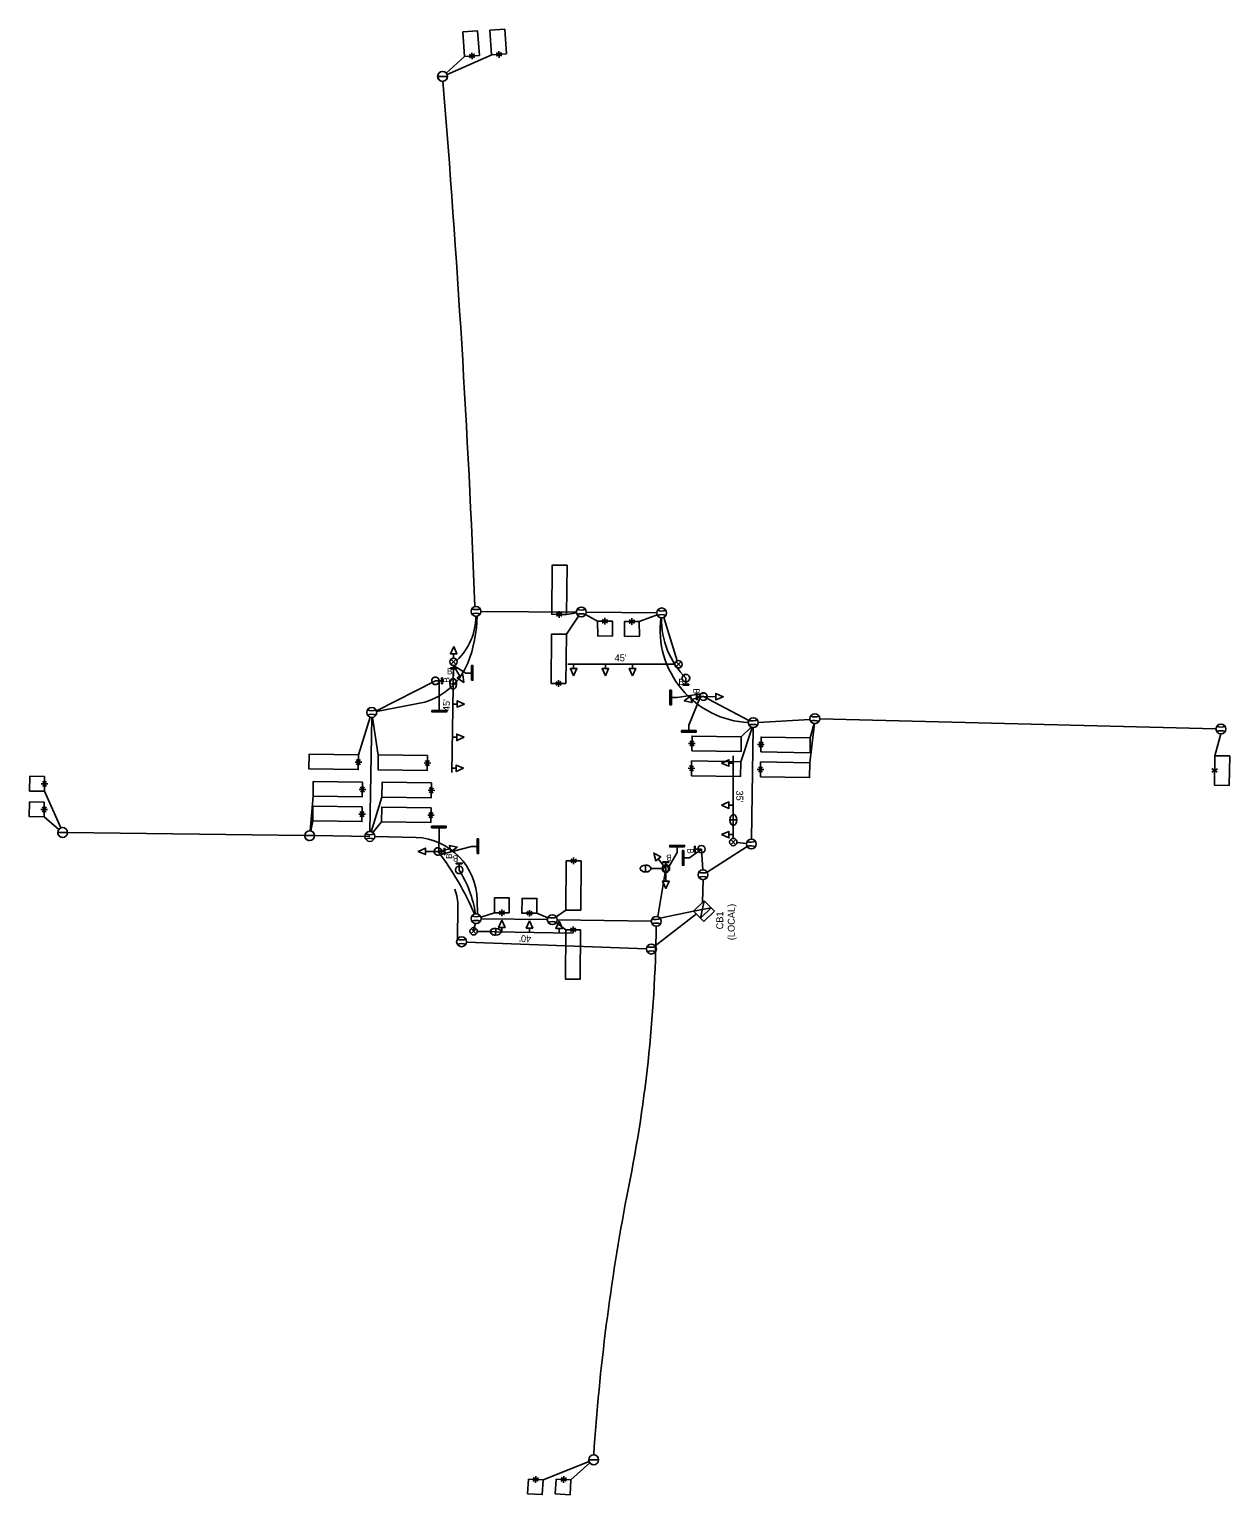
# Model space of a CAD drawing. Extents: x 596176 to 605330, y 332416 to 402398.
# Drawn here: x 604842 to 605330, y 332416 to 333011 of the extents above; entities that cross this region are included whole.
import ezdxf

# ---------------------------------------------------------------- set-up
doc = ezdxf.new("R2010")
doc.units = 0
for name, color, linetype in [('P_LTG', 7, 'Continuous'), ('P_SIG', 7, 'Continuous'), ('P_SIG_Bold', 7, 'Continuous'), ('P_SIG_Conduit', 7, 'Continuous'), ('P_SIG_IC', 7, 'Continuous'), ('P_SIG_Loops', 7, 'Continuous'), ('P_SIG_Text', 7, 'Continuous')]:
    doc.layers.add(name, color=color, linetype=linetype)

# ---------------------------------------------------------------- blocks, each defined once
blk = doc.blocks.new('CONTROL CABINET')
at = {"layer": 'P_SIG'}
for p, q in [((-0.229, 0.305), (0.229, 0.305)), ((-0.229, -0.152), (-0.229, 0.305)), ((-0.229, 0.152), (0.229, 0.152)), ((-0.229, -0.152), (0.229, 0.152)), ((0.229, -0.152), (-0.229, 0.152)), ((0.229, 0.305), (0.229, -0.152)), ((0.229, -0.152), (-0.229, -0.152))]:
    blk.add_line(p, q, dxfattribs=at)
blk = doc.blocks.new('BASE - PEDESTRIAN')
at = {"layer": 'P_SIG'}
blk.add_circle((0, 0.1), 4.57, dxfattribs=at)
blk = doc.blocks.new('_U332')
at = {"layer": 'P_SIG_Bold'}
for p, q in [((-3.429, 0), (-0.114, 0)), ((-0.081, 0.081), (0.081, -0.081)), ((0.081, 0.081), (-0.081, -0.081))]:
    blk.add_line(p, q, dxfattribs=at)
blk.add_circle((0, 0), 0.114, dxfattribs=at)
blk.add_text("45'", height=0.2134, dxfattribs=at).set_placement((-1.978, 0.092))
blk = doc.blocks.new('HEAD - TEMPORARY')
at = {"layer": 'P_SIG'}
blk.add_line((5.4, 0), (0, 0), dxfattribs=at)
blk.add_lwpolyline([(14.4, 0), (5.4, -4), (5.4, 4)], close=True, dxfattribs=at)
blk = doc.blocks.new('_U227')
at = {"layer": 'P_SIG'}
blk.add_circle((0, 0), 6.1, dxfattribs=at)
for centre, start, end in [((-15.5, 0.1), 336.6741, 22.5272), ((15.5, 0.1), 157.5751, 203.4282)]:
    blk.add_arc(centre, 13.3, start, end, dxfattribs=at)
blk = doc.blocks.new('_U226')
at = {"layer": 'P_SIG'}
blk.add_line((0, 6.1), (0, -6.1), dxfattribs=at)
blk.add_lwpolyline([(0, -6.1), (0, 6.1)], dxfattribs=at)
blk.add_circle((0, 0), 6.1, dxfattribs=at)
for start, end in [(89.7008, 180), (180, 269.7008)]:
    blk.add_arc((0, 0), 6.1, start, end, dxfattribs=at)
blk = doc.blocks.new('_U306')
at = {"layer": 'P_SIG_Loops'}
for p, q in [((-0.055, -0.084), (0.052, 0.081)), ((0.056, -0.083), (-0.053, 0.082)), ((0, 0), (0, -0.229)), ((-0.105, -0.001), (0.099, -0.001))]:
    blk.add_line(p, q, dxfattribs=at)
blk.add_lwpolyline([(0, -0.229), (1.524, -0.229), (1.524, 0.229), (0, 0.229)], close=True, dxfattribs=at)
blk = doc.blocks.new('_U325')
at = {"layer": 'P_SIG_Loops'}
for p, q in [((-0.055, -0.084), (0.052, 0.081)), ((0.056, -0.083), (-0.053, 0.082)), ((-0.105, -0.001), (0.099, -0.001))]:
    blk.add_line(p, q, dxfattribs=at)
blk.add_lwpolyline([(0, -0.229), (0.762, -0.229), (0.762, 0.229), (0, 0.229)], close=True, dxfattribs=at)
blk = doc.blocks.new('_U312')
at = {"layer": 'P_SIG_Loops'}
for p, q in [((-0.055, -0.084), (0.052, 0.081)), ((0.056, -0.083), (-0.053, 0.082)), ((0, 0), (0, -0.229)), ((-0.105, -0.001), (0.099, -0.001))]:
    blk.add_line(p, q, dxfattribs=at)
blk.add_lwpolyline([(0, -0.229), (0.457, -0.229), (0.457, 0.229), (0, 0.229)], close=True, dxfattribs=at)
blk = doc.blocks.new('_U337')
at = {"layer": 'P_SIG_Bold'}
for p, q in [((-2.667, 0), (-0.114, 0)), ((-0.081, 0.081), (0.081, -0.081)), ((0.081, 0.081), (-0.081, -0.081))]:
    blk.add_line(p, q, dxfattribs=at)
blk.add_circle((0, 0), 0.114, dxfattribs=at)
blk.add_text("35'", height=0.2134, dxfattribs=at).set_placement((-1.597, 0.092))
blk = doc.blocks.new('_U304')
at = {"layer": 'P_SIG_Bold'}
for p, q in [((-3.048, 0), (-0.114, 0)), ((-0.081, 0.081), (0.081, -0.081)), ((0.081, 0.081), (-0.081, -0.081))]:
    blk.add_line(p, q, dxfattribs=at)
blk.add_circle((0, 0), 0.114, dxfattribs=at)
blk.add_text("40'", height=0.2134, dxfattribs=at).set_placement((-1.787, 0.092))
blk = doc.blocks.new('_U330')
at = {"layer": 'P_SIG_Bold'}
for p, q in [((-3.429, 0), (-0.114, 0)), ((-0.081, 0.081), (0.081, -0.081)), ((0.081, 0.081), (-0.081, -0.081))]:
    blk.add_line(p, q, dxfattribs=at)
blk.add_circle((0, 0), 0.114, dxfattribs=at)
blk.add_text("45'", height=0.2134, dxfattribs=at).set_placement((-1.528, 0.092))

msp = doc.modelspace()

# ---------------------------------------------------------------- linework, layer by layer
at = {"layer": 'P_LTG'}
for p, q in [((605014.67, 332752.47), (605014.59, 332747.18)), ((605013.15, 332745.01), (605015.93, 332744.96)), ((605129.73, 332689.77), (605126.96, 332689.77)), ((605128.33, 332682.28), (605128.33, 332687.58)), ((605092.7, 332671.4), (605092.7, 332668.63)), ((605100.19, 332670), (605094.89, 332670)), ((605031.78, 332642.95), (605031.84, 332645.73)), ((605024.32, 332644.5), (605029.62, 332644.4))]:
    msp.add_line(p, q, dxfattribs=at)
msp.add_circle((605100.89, 332670), 1.21, dxfattribs=at)
for centre, major_axis in [((605014.54, 332744.99), (-0.03, -2.18)), ((605128.34, 332689.77), (0, 2.18)), ((605092.7, 332670.02), (-2.18, 0)), ((605031.81, 332644.34), (2.18, -0.04))]:
    msp.add_ellipse(centre, major_axis=major_axis, ratio=0.636439, dxfattribs=at)
for centre, major_axis in [((605014.54, 332744.99), (-0.03, -2.18)), ((605128.34, 332689.77), (0, 2.18)), ((605092.7, 332670.02), (-2.18, 0)), ((605031.81, 332644.34), (2.18, -0.04))]:
    msp.add_ellipse(centre, major_axis=major_axis, ratio=0.636439, start_param=1.570796, end_param=4.712389, dxfattribs=at)
at = {"layer": 'P_SIG'}
for p, q in [((605019.67, 332749.43), (605014.67, 332752.47)), ((605017.29, 332748.14), (605014.67, 332752.47)), ((605019.67, 332749.43), (605022.07, 332749.43)), ((605109.09, 332747.36), (605109.09, 332744.86)), ((605007.35, 332746.25), (605009.85, 332746.25)), ((605008.85, 332736.46), (605008.9, 332746.25)), ((605105.46, 332739.52), (605116.1, 332741.08)), ((605008.85, 332736.46), (605008.85, 332734.06)), ((605102.26, 332739.29), (605102.6, 332739.48)), ((605105.46, 332739.52), (605103.06, 332739.52)), ((605110.24, 332728.3), (605114.94, 332739.84)), ((605111.26, 332738.74), (605116.19, 332739.84)), ((605116.19, 332739.84), (605113.69, 332739.84)), ((605121.25, 332739.82), (605116.19, 332739.84)), ((605110.24, 332728.3), (605110.24, 332725.9)), ((605008.78, 332684.35), (605008.7, 332677.17)), ((605008.78, 332684.35), (605008.78, 332686.75)), ((605003.28, 332676.98), (605008.34, 332676.97)), ((605013.27, 332678.07), (605008.34, 332676.96)), ((605008.34, 332676.97), (605010.84, 332676.97)), ((605021.98, 332679.03), (605008.5, 332675.46)), ((605021.98, 332679.03), (605024.38, 332679.03)), ((605105.55, 332676.54), (605101.79, 332669.99)), ((605105.55, 332676.54), (605105.55, 332678.94)), ((605110.53, 332674.38), (605115.37, 332677.88)), ((605115.37, 332677.88), (605112.87, 332677.88)), ((605017, 332669.42), (605017, 332671.92)), ((605097.84, 332673.98), (605100.94, 332669.99)), ((605100.93, 332664.93), (605100.94, 332669.99)), ((605100.94, 332669.99), (605100.94, 332672.49)), ((605110.53, 332674.38), (605108.13, 332674.38))]:
    msp.add_line(p, q, dxfattribs=at)
for points in [[(605009.85, 332745.05), (605009.85, 332747.45), (605010.18, 332747.45), (605010.18, 332745.05)], [(605013.47, 332751.47), (605015.87, 332751.47), (605015.87, 332751.15), (605013.47, 332751.15)], [(605021.93, 332746.47), (605021.93, 332752.47), (605022.53, 332752.47), (605022.53, 332746.47)], [(605103.2, 332742.48), (605103.2, 332736.48), (605102.6, 332736.48), (605102.6, 332742.48)], [(605107.89, 332744.86), (605110.29, 332744.86), (605110.29, 332744.53), (605107.89, 332744.53)], [(605113.69, 332741.04), (605113.69, 332738.64), (605113.36, 332738.64), (605113.36, 332741.04)], [(605005.9, 332734.2), (605011.9, 332734.2), (605011.9, 332733.6), (605005.9, 332733.6)], [(605107.28, 332726.03), (605113.28, 332726.04), (605113.28, 332725.43), (605107.28, 332725.43)], [(605011.73, 332686.62), (605005.73, 332686.61), (605005.73, 332687.22), (605011.73, 332687.22)], [(605024.25, 332676.07), (605024.25, 332682.07), (605024.85, 332682.07), (605024.85, 332676.07)], [(605010.84, 332675.77), (605010.84, 332678.17), (605011.16, 332678.17), (605011.16, 332675.77)], [(605108.5, 332678.81), (605102.5, 332678.81), (605102.5, 332679.41), (605108.51, 332679.41)], [(605108.27, 332677.34), (605108.27, 332671.34), (605107.67, 332671.34), (605107.67, 332677.34)], [(605112.89, 332679.08), (605112.89, 332676.68), (605112.57, 332676.68), (605112.57, 332679.08)], [(605018.2, 332671.92), (605015.8, 332671.92), (605015.8, 332672.25), (605018.2, 332672.25)], [(605102.14, 332672.48), (605099.74, 332672.48), (605099.74, 332672.81), (605102.14, 332672.81)]]:
    msp.add_lwpolyline(points, close=True, dxfattribs=at)
for points in [[(605018.82, 332745.61), (605016.16, 332747.46), (605018.41, 332748.83), (605018.82, 332745.61)], [(605018.82, 332745.61), (605016.16, 332747.46), (605018.41, 332748.83), (605018.82, 332745.61)], [(605016.16, 332747.46), (605018.82, 332745.61), (605018.41, 332748.83), (605016.16, 332747.46)], [(605124.21, 332739.82), (605121.25, 332738.51), (605121.25, 332741.14), (605124.21, 332739.82)], [(605121.25, 332738.51), (605124.21, 332739.82), (605121.25, 332741.14), (605121.25, 332738.51)], [(605108.37, 332738.08), (605110.96, 332740.02), (605111.55, 332737.45), (605108.37, 332738.08)], [(605110.96, 332740.02), (605108.37, 332738.08), (605111.55, 332737.45), (605110.96, 332740.02)], [(605000.32, 332676.98), (605003.28, 332678.3), (605003.28, 332675.66), (605000.32, 332676.98)], [(605003.28, 332678.3), (605000.32, 332676.98), (605003.28, 332675.66), (605003.28, 332678.3)], [(605016.16, 332678.72), (605013.56, 332676.79), (605012.98, 332679.35), (605016.16, 332678.72)], [(605013.56, 332676.79), (605016.16, 332678.72), (605012.98, 332679.35), (605013.56, 332676.79)], [(605096.02, 332676.32), (605098.88, 332674.79), (605096.8, 332673.17), (605096.02, 332676.32)], [(605098.88, 332674.79), (605096.02, 332676.32), (605096.8, 332673.17), (605098.88, 332674.79)], [(605100.93, 332661.97), (605099.61, 332664.93), (605102.25, 332664.93), (605100.93, 332661.97)], [(605099.61, 332664.93), (605100.93, 332661.97), (605102.25, 332664.93), (605099.61, 332664.93)]]:
    msp.add_lwpolyline(points, dxfattribs=at)
for centre in [(605007.32, 332746.24), (605109.08, 332747.37), (605116.19, 332739.84), (605116.19, 332739.84), (605116.19, 332739.84), (605116.19, 332739.84), (605116.19, 332739.84), (605116.19, 332739.84), (605008.34, 332676.97), (605008.34, 332676.97), (605008.34, 332676.97), (605008.34, 332676.96), (605008.34, 332676.96), (605008.34, 332676.96), (605100.94, 332669.99), (605100.94, 332669.99), (605100.94, 332669.99), (605100.94, 332669.99), (605100.94, 332669.99), (605100.94, 332669.99)]:
    msp.add_circle(centre, 1.52, dxfattribs=at)
for centre, start, end in [((605007.32, 332746.24), 12.77542, 192.77542), ((605109.08, 332747.37), 12.77542, 192.77542), ((605109.08, 332747.37), 192.77542, 12.77542), ((605007.32, 332746.24), 192.77542, 12.77542), ((605116.19, 332739.84), 12.77542, 192.77542), ((605116.19, 332739.84), 0, 180), ((605116.19, 332739.84), 180, 0), ((605116.19, 332739.84), 192.77542, 12.77542), ((605008.34, 332676.97), 0, 180), ((605008.34, 332676.96), 12.77542, 192.77542), ((605008.34, 332676.97), 180, 0), ((605008.34, 332676.96), 192.77542, 12.77542), ((605100.94, 332669.99), 90, 270), ((605100.94, 332669.99), 127.91062, 307.91062), ((605100.94, 332669.99), 307.91062, 127.91062), ((605100.94, 332669.99), 270, 90)]:
    msp.add_arc(centre, 1.52, start, end, dxfattribs=at)
at = {"layer": 'P_SIG_Conduit'}
for p, q in [((605100.08, 332772.04), (605105.52, 332754.37)), ((604857.91, 332684.65), (604954.25, 332683.48))]:
    msp.add_line(p, q, dxfattribs=at)
for points in [[(605025.8, 332774.43), (605064.64, 332774.17)], [(605068.64, 332774.14), (605097.22, 332773.87)], [(604983.34, 332734.06), (605007.35, 332746.25)], [(604983.41, 332733.8), (605003.04, 332737.58)], [(605134.62, 332730.15), (605115.99, 332739.99)], [(604980.7, 332685.05), (604981.48, 332731.41)], [(605159.48, 332730.49), (605138.41, 332729.37)], [(605163.44, 332730.81), (605324.39, 332726.76)], [(605136.38, 332727.27), (605135.67, 332681.99)], [(604980.66, 332683.05), (604958.25, 332683.4)], [(604999.49, 332682.65), (604982.66, 332683.06)], [(605115.91, 332669.49), (605115.37, 332677.88)], [(605117.72, 332668.57), (605133.92, 332678.96)], [(605133.65, 332680.2), (605129.82, 332680.62)], [(605097.64, 332650.48), (605100.94, 332669.99)], [(605115.82, 332656.32), (605116.1, 332665.49)], [(605024.35, 332651.63), (605024.23, 332657.08)], [(605098.49, 332649.92), (605112.22, 332652.71)], [(605023.55, 332647.71), (605022.7, 332644.66)], [(605052.78, 332649.26), (605025.86, 332649.66)], [(605095, 332648.62), (605056.77, 332649.2)]]:
    msp.add_lwpolyline(points, dxfattribs=at)
for centre, radius, start, end in [((600031.92, 332578.64), 4995.36, 2.26878, 4.72053), ((604998.97, 332772.55), 24.8, 313.50097, 359.73302), ((604966.45, 332774.16), 57.88, 339.01149, 358.35226), ((605136.43, 332767.07), 37.83, 172.70123, 266.94557), ((605132.81, 332771.29), 33.69, 179.04506, 225.25617), ((604995.05, 332763.89), 27.49, 286.88731, 337.65014), ((604998.4, 332656.85), 25.83, 0.51444, 87.58484), ((604908.2, 332601.7), 125.34, 23.44659, 36.90431), ((604976.23, 332644.18), 47.95, 8.99215, 31.76773), ((604529.61, 332652.95), 567.41, 348.2085, 359.35788), ((605948.01, 332373.18), 878.37, 169.25156, 176.16781)]:
    msp.add_arc(centre, radius, start, end, dxfattribs=at)
at = {"layer": 'P_SIG_IC'}
msp.add_line((605019.94, 332640.16), (605093.06, 332637.39), dxfattribs=at)
for points in [[(605016.29, 332641.42), (605016.46, 332654.32)], [(605096.54, 332638.66), (605113.33, 332651.58)]]:
    msp.add_lwpolyline(points, dxfattribs=at)
msp.add_arc((604996.47, 332654.58), 20, 359.2508, 20.66715, dxfattribs=at)
at = {"layer": 'P_SIG_Loops'}
for p, q in [((605011.66, 332993.1), (605019.17, 332999.84)), ((605012.05, 332992.51), (605030.17, 333000.48)), ((605065.44, 332772.57), (605060.5, 332765.18)), ((605064.58, 332773.9), (605060.58, 332773.22)), ((605068.29, 332773.24), (605073.18, 332770.46)), ((605090.08, 332770.36), (605097.39, 332773.06)), ((604976.04, 332716.24), (604980.85, 332731.5)), ((604984.09, 332716.13), (604981.76, 332731.43)), ((605131.4, 332713.42), (605135.96, 332727.32)), ((605135.54, 332727.47), (605131.56, 332723.5)), ((605161.26, 332728.89), (605159.43, 332712.98)), ((605159.6, 332723.06), (605161.12, 332728.9)), ((605326.36, 332724.71), (605323.97, 332715.86)), ((605323.88, 332711.23), (605323.84, 332708.56)), ((605322.77, 332709.14), (605324.96, 332710.54)), ((605322.78, 332710.6), (605324.93, 332709.16)), ((604855.1, 332686.49), (604848.47, 332701.42)), ((604957.61, 332699.42), (604956.42, 332685.38)), ((604981.27, 332684.96), (604985.61, 332699.04)), ((604848.34, 332690.99), (604854.38, 332685.94)), ((604956.64, 332685.35), (604957.46, 332689.37)), ((604985.45, 332688.99), (604981.92, 332684.61)), ((605031.29, 332652.1), (605025.76, 332650.3)), ((605052.93, 332650), (605048.49, 332651.86)), ((605060.35, 332653.18), (605056.41, 332650.38)), ((605056.38, 332648.04), (605060.31, 332645.14)), ((605069.73, 332429.15), (605051.07, 332421.73)), ((605062.38, 332421.71), (605070.05, 332428.61))]:
    msp.add_line(p, q, dxfattribs=at)
msp.add_lwpolyline([(605323.97, 332715.86), (605323.82, 332703.86), (605329.82, 332703.78), (605329.97, 332715.78)], close=True, dxfattribs=at)

# ---------------------------------------------------------------- block references
at = {"layer": 'P_SIG'}
for name, p, xscale, yscale, rotation in [('HEAD - TEMPORARY', (605014.7, 332755.47), 0.32808333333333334, 0.32808333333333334, 89.13535792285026), ('_U330', (605014.67, 332753.97), 13.123333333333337, 13.123333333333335, 89.13535792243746), ('HEAD - TEMPORARY', (605063.46, 332752.98), 0.32808333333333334, 0.32808333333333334, -90.00000000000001), ('HEAD - TEMPORARY', (605076.35, 332752.98), 0.32808333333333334, 0.32808333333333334, -90.00000000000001), ('HEAD - TEMPORARY', (605087.39, 332752.98), 0.32808333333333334, 0.32808333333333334, -90.00000000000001), ('HEAD - TEMPORARY', (605128.31, 332712.88), 0.32808333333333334, 0.32808333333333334, 180), ('_U337', (605128.33, 332680.78), 13.123333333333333, 13.123333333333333, -90.00000000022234), ('HEAD - TEMPORARY', (605128.31, 332695.75), 0.32808333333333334, 0.32808333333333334, 180), ('HEAD - TEMPORARY', (605128.31, 332683.78), 0.32808333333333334, 0.32808333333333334, 180), ('CONTROL CABINET', (605115.73, 332653.43), 13.123333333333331, 13.12333333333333, -135.37543928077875), ('CONTROL CABINET', (605115.73, 332653.43), 13.123333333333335, 13.123333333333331, -135.29557835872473), ('_U304', (605022.83, 332644.54), 13.123333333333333, 13.12333333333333, 178.87701025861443), ('HEAD - TEMPORARY', (605034.31, 332644.32), 0.32808333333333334, 0.32808333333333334, 90), ('HEAD - TEMPORARY', (605045.51, 332644.1), 0.32808333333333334, 0.32808333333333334, 90), ('HEAD - TEMPORARY', (605057.59, 332643.86), 0.32808333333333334, 0.32808333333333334, 90)]:
    msp.add_blockref(name, p, dxfattribs=dict(at, xscale=xscale, yscale=yscale, rotation=rotation))
at = {"layer": 'P_SIG', "xscale": 0.32808333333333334, "yscale": 0.32808333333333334}
for name, p in [('HEAD - TEMPORARY', (605014.41, 332736.84)), ('HEAD - TEMPORARY', (605014.21, 332723.32)), ('HEAD - TEMPORARY', (605014.02, 332710.72)), ('BASE - PEDESTRIAN', (605115.37, 332677.88)), ('BASE - PEDESTRIAN', (605017, 332669.42))]:
    msp.add_blockref(name, p, dxfattribs=at)
at = {"layer": 'P_SIG_Bold', "xscale": 13.123333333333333, "yscale": 13.123333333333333}
msp.add_blockref('_U332', (605106.07, 332752.98), dxfattribs=at)
at = {"layer": 'P_SIG_Conduit', "xscale": 0.32808333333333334, "yscale": 0.32808333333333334, "rotation": 90}
for name, p in [('_U226', (605010.21, 332991.73)), ('_U227', (605023.81, 332774.44)), ('_U227', (605066.56, 332774.23)), ('_U227', (605099.23, 332773.85)), ('_U227', (604981.46, 332733.41)), ('_U227', (605136.42, 332729.27)), ('_U227', (605161.44, 332730.88)), ('_U227', (605326.39, 332726.71)), ('_U226', (604855.92, 332684.66)), ('_U226', (604956.25, 332683.39)), ('_U227', (604980.67, 332683.05)), ('_U227', (605135.64, 332679.99)), ('_U227', (605116.04, 332667.49)), ('_U227', (605023.86, 332649.69)), ('_U227', (605054.78, 332649.23)), ('_U227', (605097.01, 332648.59)), ('_U226', (605071.59, 332429.89))]:
    msp.add_blockref(name, p, dxfattribs=at)
at = {"layer": 'P_SIG_IC', "xscale": 0.32808333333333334, "yscale": 0.32808333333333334, "rotation": 90}
for p in [(605017.94, 332640.28), (605095.06, 332637.31)]:
    msp.add_blockref('_U227', p, dxfattribs=at)
at = {"layer": 'P_SIG_Loops'}
for name, p, xscale, yscale, rotation in [('_U325', (605022.16, 333000.05), 13.123333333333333, 13.12333333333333, 93.96673151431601), ('_U325', (605033.16, 333000.68), 13.123333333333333, 13.12333333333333, 93.87701958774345), ('_U306', (605057.58, 332773.25), 13.123333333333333, 13.123333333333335, 89.45794576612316), ('_U312', (605076.18, 332770.49), 13.123333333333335, 13.123333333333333, -89.31932784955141), ('_U312', (605087.08, 332770.33), 13.123333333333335, 13.123333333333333, -89.31932784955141), ('_U306', (605057.31, 332745.21), 13.123333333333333, 13.123333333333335, 89.45794576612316), ('_U306', (605111.51, 332720.82), 13.123333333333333, 13.123333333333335, -0.8970914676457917), ('_U306', (605139.56, 332720.38), 13.123333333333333, 13.123333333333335, -0.8970914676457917), ('_U306', (604976, 332713.24), 13.123333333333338, 13.123333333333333, 179.2211160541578), ('_U306', (605004.04, 332712.86), 13.123333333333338, 13.123333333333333, 179.2211160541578), ('_U306', (605111.36, 332710.73), 13.123333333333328, 13.12333333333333, -0.8970832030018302), ('_U306', (605139.38, 332710.3), 13.123333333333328, 13.12333333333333, -0.8970832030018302), ('_U312', (604848.51, 332704.42), 13.123333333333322, 13.123333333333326, 179.17384230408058), ('_U306', (604977.65, 332702.15), 13.123333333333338, 13.123333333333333, 179.2211160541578), ('_U306', (605005.64, 332701.77), 13.123333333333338, 13.123333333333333, 179.2211160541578), ('_U312', (604848.39, 332693.99), 13.123333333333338, 13.123333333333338, 178.99878615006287), ('_U306', (604977.5, 332692.1), 13.123333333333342, 13.123333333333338, 179.2211160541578), ('_U306', (605005.49, 332691.72), 13.123333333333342, 13.123333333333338, 179.2211160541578), ('_U306', (605063.48, 332673.16), 13.123333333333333, 13.123333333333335, -90.3829651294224), ('_U312', (605034.29, 332652.08), 13.123333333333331, 13.123333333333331, 89.76700985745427), ('_U312', (605045.49, 332651.87), 13.123333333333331, 13.123333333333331, 89.76700985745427), ('_U306', (605063.29, 332645.12), 13.123333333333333, 13.123333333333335, -90.3829651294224), ('_U312', (605048.08, 332421.9), 13.123333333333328, 13.123333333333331, -93.30067811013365), ('_U312', (605059.39, 332421.9), 13.12333333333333, 13.12333333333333, -93.62438316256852)]:
    msp.add_blockref(name, p, dxfattribs=dict(at, xscale=xscale, yscale=yscale, rotation=rotation))

# ---------------------------------------------------------------- texts
at = {"layer": 'P_SIG'}
for rotation, p in [(90, (605013.06, 332745.46)), (360, (605012, 332748.9)), (360, (605106.05, 332744.55)), (270, (605112.08, 332743.15)), (90, (605014.12, 332673.93)), (180, (605103.35, 332675.69)), (270, (605109.68, 332678.23)), (180, (605016.59, 332675.36))]:
    msp.add_text('B', height=2.52, rotation=rotation, dxfattribs=at).set_placement(p)
at = {"layer": 'P_SIG_Text'}
for s, p in [('CB1', (605124.23, 332645.33)), ('(LOCAL)', (605128.9, 332640.92))]:
    msp.add_text(s, height=2.8, rotation=90, dxfattribs=at).set_placement(p)

doc.saveas('drawing.dxf')
